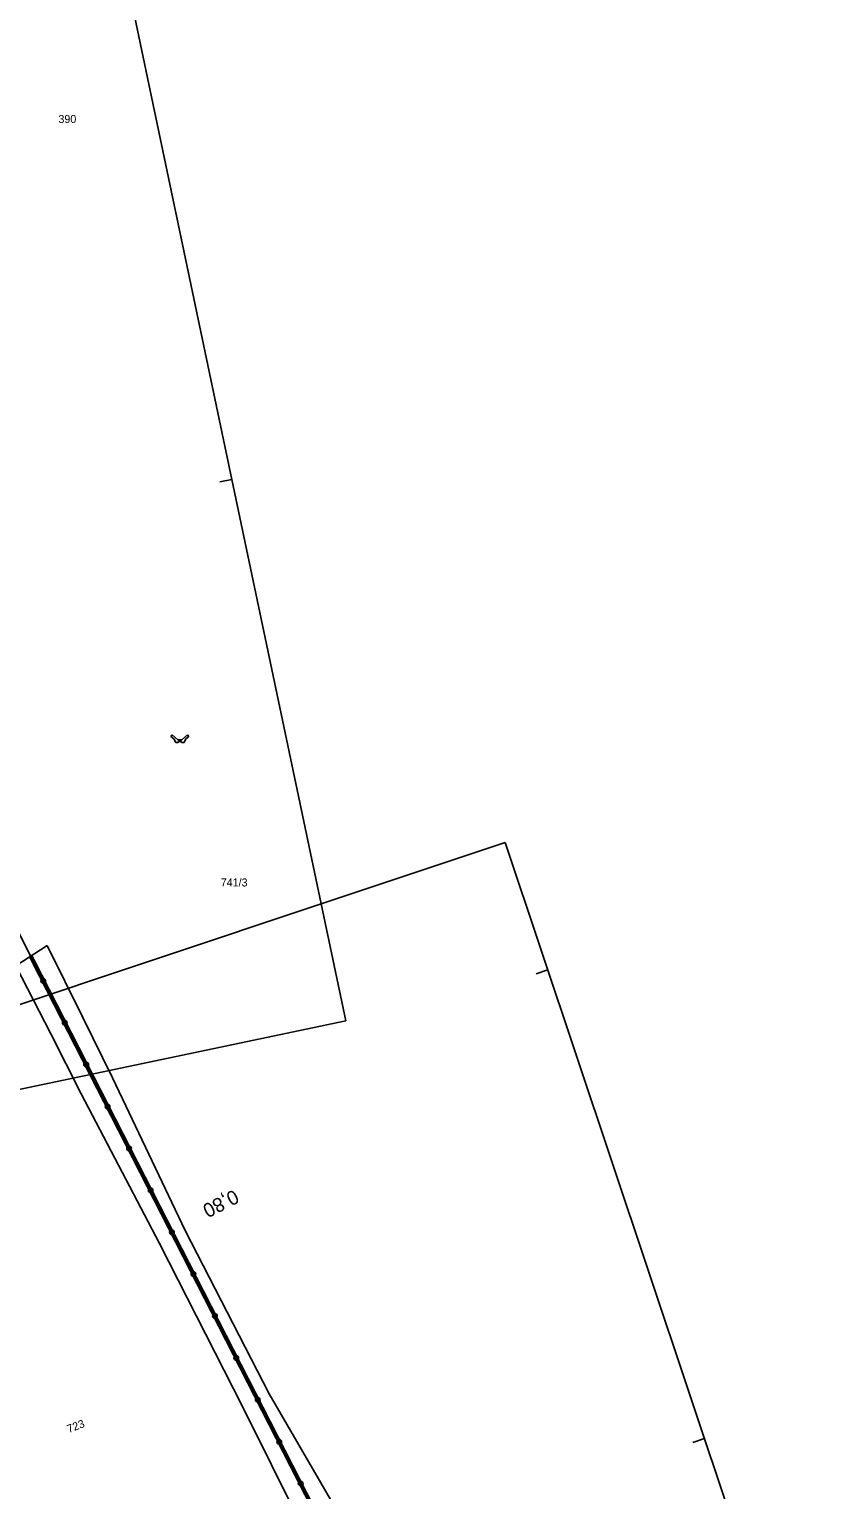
# Model space of a CAD drawing. Extents: x -548552 to -543113, y -1131925 to -1123599.
# Drawn here: x -547500.3 to -547331.6, y -1126015.1 to -1125704.8 of the extents above; entities that cross this region are included whole.
import ezdxf

# ---------------------------------------------------------------- set-up
doc = ezdxf.new("R2010")
doc.units = 0
for name, color, linetype in [('Parcelní čísla', 7, 'Continuous'), ('Profile', 7, 'Continuous'), ('PROFILY NÁVRH', 7, 'Continuous'), ('STANIČENÍ', 7, 'Continuous')]:
    doc.layers.add(name, color=color, linetype=linetype)

msp = doc.modelspace()

# ---------------------------------------------------------------- linework, layer by layer
at = {"layer": 'Profile'}
for p, q in [((-547481.39, -1125685.38), (-547457.23, -1125800.45)), ((-547457.23, -1125800.45), (-547459.81, -1125800.99)), ((-547457.23, -1125800.45), (-547438.29, -1125890.64)), ((-547438.29, -1125890.64), (-547399.21, -1125877.58)), ((-547399.21, -1125877.58), (-547368.83, -1125968.44)), ((-547540.05, -1125924.66), (-547438.29, -1125890.64)), ((-547438.29, -1125890.64), (-547433.07, -1125915.52)), ((-547390.16, -1125904.64), (-547392.66, -1125905.48)), ((-547535.88, -1125937.11), (-547433.07, -1125915.52)), ((-547368.83, -1125968.44), (-547331.56, -1126079.95)), ((-547356.87, -1126004.22), (-547359.38, -1126005.06))]:
    msp.add_line(p, q, dxfattribs=at)
at = {"layer": 'PROFILY NÁVRH'}
for p, q in [((-547470.19, -1125855.06), (-547469.94, -1125854.75)), ((-547470.19, -1125855.06), (-547469.56, -1125855.56)), ((-547469.94, -1125854.75), (-547468.69, -1125855.75)), ((-547469.56, -1125855.56), (-547469.17, -1125856.35)), ((-547469.17, -1125856.35), (-547468.67, -1125856.35)), ((-547468.69, -1125855.75), (-547467.89, -1125855.75)), ((-547468.67, -1125856.35), (-547468.57, -1125856.15)), ((-547468.57, -1125856.15), (-547468.01, -1125856.15)), ((-547467.91, -1125856.35), (-547468.01, -1125856.15)), ((-547467.41, -1125856.35), (-547467.91, -1125856.35)), ((-547467.89, -1125855.75), (-547466.64, -1125854.75)), ((-547467.01, -1125855.56), (-547467.41, -1125856.35)), ((-547466.39, -1125855.06), (-547467.01, -1125855.56)), ((-547466.39, -1125855.06), (-547466.64, -1125854.75)), ((-547503.09, -1125903.83), (-547496.5, -1125899.51)), ((-547496.5, -1125899.51), (-547488.91, -1125914.78)), ((-547499.63, -1125902.98), (-547500.17, -1125901.91)), ((-547499.18, -1125902.75), (-547499.75, -1125901.64)), ((-547356.19, -1126183.35), (-547499.63, -1125902.98)), ((-547355.74, -1126183.12), (-547499.18, -1125902.75)), ((-547503.09, -1125903.83), (-547495.71, -1125918.26)), ((-547488.91, -1125914.78), (-547482.58, -1125927.63)), ((-547495.71, -1125918.26), (-547489.23, -1125931.03)), ((-547482.58, -1125927.63), (-547467.17, -1125960.04)), ((-547489.23, -1125931.03), (-547472.59, -1125962.81)), ((-547467.17, -1125960.04), (-547449.32, -1125994.74)), ((-547472.59, -1125962.81), (-547454.91, -1125997.6)), ((-547449.32, -1125994.74), (-547433.76, -1126021.6)), ((-547454.91, -1125997.6), (-547441.1, -1126025.35))]:
    msp.add_line(p, q, dxfattribs=at)
at = {"layer": 'STANIČENÍ'}
for p, q in [((-547499.86, -1125901.97), (-547505.07, -1125891.79)), ((-547499.4, -1125902.86), (-547499.86, -1125901.97)), ((-547355.97, -1126183.23), (-547499.4, -1125902.86)), ((-547488.58, -1125915.43), (-547489.13, -1125914.36)), ((-547482.3, -1125928.17), (-547482.87, -1125927.05)), ((-547466.9, -1125960.59), (-547467.45, -1125959.5)), ((-547472.51, -1125962.97), (-547472.68, -1125962.63)), ((-547448.98, -1125995.41), (-547449.52, -1125994.36)), ((-547454.79, -1125997.84), (-547455.04, -1125997.35))]:
    msp.add_line(p, q, dxfattribs=at)
for centre, radius in [((-547500.04, -1125901.63), 0.1), ((-547499.58, -1125902.51), 0.1), ((-547499.13, -1125903.39), 0.1), ((-547498.68, -1125904.28), 0.1), ((-547498.22, -1125905.17), 0.1), ((-547497.76, -1125906.07), 0.1), ((-547497.3, -1125906.98), 0.5), ((-547497.31, -1125906.96), 0.1), ((-547496.85, -1125907.85), 0.1), ((-547496.4, -1125908.74), 0.1), ((-547495.94, -1125909.63), 0.1), ((-547495.49, -1125910.52), 0.1), ((-547495.03, -1125911.41), 0.1), ((-547494.58, -1125912.3), 0.1), ((-547494.12, -1125913.19), 0.1), ((-547493.67, -1125914.08), 0.1), ((-547493.21, -1125914.97), 0.1), ((-547492.74, -1125915.88), 0.5), ((-547492.75, -1125915.86), 0.1), ((-547492.3, -1125916.75), 0.1), ((-547491.84, -1125917.64), 0.1), ((-547491.39, -1125918.53), 0.1), ((-547490.93, -1125919.42), 0.1), ((-547490.48, -1125920.31), 0.1), ((-547490.02, -1125921.2), 0.1), ((-547489.57, -1125922.09), 0.1), ((-547489.11, -1125922.98), 0.1), ((-547488.66, -1125923.87), 0.1), ((-547488.19, -1125924.79), 0.5), ((-547488.2, -1125924.76), 0.1), ((-547487.74, -1125925.65), 0.1), ((-547487.29, -1125926.54), 0.1), ((-547486.83, -1125927.43), 0.1), ((-547486.38, -1125928.32), 0.1), ((-547485.92, -1125929.21), 0.1), ((-547485.47, -1125930.1), 0.1), ((-547485.01, -1125930.99), 0.1), ((-547484.56, -1125931.88), 0.1), ((-547484.1, -1125932.77), 0.1), ((-547483.63, -1125933.69), 0.5), ((-547483.65, -1125933.66), 0.1), ((-547483.19, -1125934.55), 0.1), ((-547482.73, -1125935.45), 0.1), ((-547482.28, -1125936.34), 0.1), ((-547481.82, -1125937.23), 0.1), ((-547481.37, -1125938.12), 0.1), ((-547480.91, -1125939.01), 0.1), ((-547480.46, -1125939.9), 0.1), ((-547480, -1125940.79), 0.1), ((-547479.55, -1125941.68), 0.1), ((-547479.08, -1125942.59), 0.5), ((-547479.09, -1125942.57), 0.1), ((-547478.63, -1125943.46), 0.1), ((-547478.18, -1125944.35), 0.1), ((-547477.72, -1125945.24), 0.1), ((-547477.27, -1125946.13), 0.1), ((-547476.81, -1125947.02), 0.1), ((-547476.36, -1125947.91), 0.1), ((-547475.9, -1125948.8), 0.1), ((-547475.45, -1125949.69), 0.1), ((-547474.99, -1125950.58), 0.1), ((-547474.52, -1125951.49), 0.5), ((-547474.54, -1125951.47), 0.1), ((-547474.08, -1125952.36), 0.1), ((-547473.62, -1125953.25), 0.1), ((-547473.17, -1125954.14), 0.1), ((-547472.71, -1125955.03), 0.1), ((-547472.26, -1125955.92), 0.1), ((-547471.8, -1125956.81), 0.1), ((-547471.35, -1125957.7), 0.1), ((-547470.89, -1125958.59), 0.1), ((-547470.44, -1125959.48), 0.1), ((-547469.97, -1125960.4), 0.5), ((-547469.98, -1125960.37), 0.1), ((-547469.53, -1125961.26), 0.1), ((-547469.07, -1125962.15), 0.1), ((-547468.61, -1125963.04), 0.1), ((-547468.16, -1125963.94), 0.1), ((-547468.15, -1125963.96), 0.1), ((-547467.7, -1125964.83), 0.1), ((-547467.69, -1125964.85), 0.1), ((-547467.25, -1125965.72), 0.1), ((-547466.79, -1125966.61), 0.1), ((-547466.34, -1125967.5), 0.1), ((-547465.88, -1125968.39), 0.1), ((-547465.41, -1125969.3), 0.5), ((-547465.43, -1125969.28), 0.1), ((-547464.97, -1125970.17), 0.1), ((-547464.52, -1125971.06), 0.1), ((-547464.06, -1125971.95), 0.1), ((-547463.6, -1125972.84), 0.1), ((-547463.15, -1125973.73), 0.1), ((-547462.69, -1125974.62), 0.1), ((-547462.24, -1125975.51), 0.1), ((-547461.78, -1125976.4), 0.1), ((-547461.33, -1125977.29), 0.1), ((-547460.86, -1125978.2), 0.5), ((-547460.87, -1125978.18), 0.1), ((-547460.42, -1125979.07), 0.1), ((-547459.96, -1125979.96), 0.1), ((-547459.5, -1125980.85), 0.1), ((-547459.05, -1125981.74), 0.1), ((-547458.59, -1125982.63), 0.1), ((-547458.14, -1125983.52), 0.1), ((-547457.68, -1125984.41), 0.1), ((-547457.23, -1125985.3), 0.1), ((-547456.77, -1125986.19), 0.1), ((-547456.31, -1125987.1), 0.5), ((-547456.32, -1125987.08), 0.1), ((-547455.86, -1125987.97), 0.1), ((-547455.41, -1125988.86), 0.1), ((-547454.95, -1125989.75), 0.1), ((-547454.49, -1125990.64), 0.1), ((-547454.04, -1125991.53), 0.1), ((-547453.58, -1125992.42), 0.1), ((-547453.13, -1125993.32), 0.1), ((-547452.67, -1125994.21), 0.1), ((-547452.22, -1125995.1), 0.1), ((-547451.75, -1125996.01), 0.5), ((-547451.76, -1125995.99), 0.1), ((-547451.31, -1125996.88), 0.1), ((-547450.85, -1125997.77), 0.1), ((-547450.4, -1125998.66), 0.1), ((-547449.94, -1125999.55), 0.1), ((-547449.48, -1126000.44), 0.1), ((-547449.03, -1126001.33), 0.1), ((-547448.57, -1126002.22), 0.1), ((-547448.12, -1126003.11), 0.1), ((-547447.66, -1126004), 0.1), ((-547447.2, -1126004.91), 0.5), ((-547447.21, -1126004.89), 0.1), ((-547446.75, -1126005.78), 0.1), ((-547446.3, -1126006.67), 0.1), ((-547445.84, -1126007.56), 0.1), ((-547445.39, -1126008.45), 0.1), ((-547444.93, -1126009.34), 0.1), ((-547444.47, -1126010.23), 0.1), ((-547444.02, -1126011.12), 0.1), ((-547443.56, -1126012.01), 0.1), ((-547443.11, -1126012.9), 0.1), ((-547442.64, -1126013.81), 0.5), ((-547442.65, -1126013.79), 0.1), ((-547442.2, -1126014.68), 0.1)]:
    msp.add_circle(centre, radius, dxfattribs=at)

# ---------------------------------------------------------------- texts
at = {"layer": 'Parcelní čísla'}
for s, p in [('390', (-547494.08, -1125724.71)), ('741/3', (-547459.61, -1125886.93))]:
    msp.add_text(s, height=1.7, dxfattribs=at).set_placement(p)
msp.add_text('723', height=1.7, rotation=21, dxfattribs=at).set_placement((-547491.88, -1126003.08))
at = {"layer": 'STANIČENÍ'}
msp.add_text('0,80', height=3, rotation=207.0941, dxfattribs=at).set_placement((-547456.78, -1125951.23))

doc.saveas('drawing.dxf')
